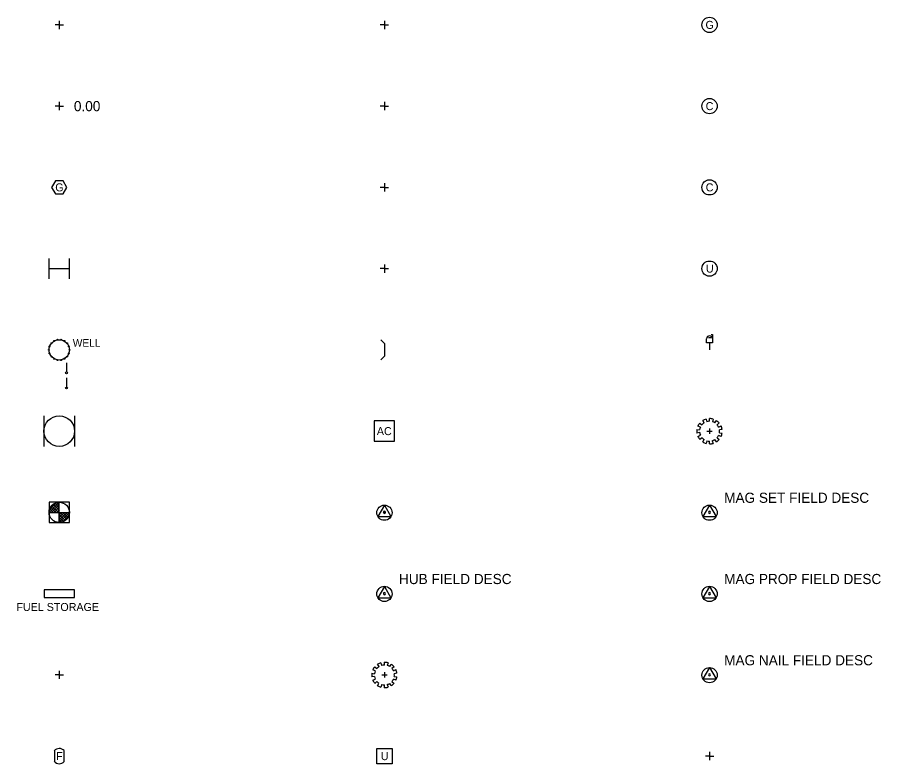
# Model space of a CAD drawing. Extents: x 91 to 2906, y -24 to 912.
# Drawn here: x 874 to 1405, y -5 to 455 of the extents above; entities that cross this region are included whole.
import ezdxf

# ---------------------------------------------------------------- set-up
doc = ezdxf.new("R2010")
doc.units = 0
for name, color, linetype in [('Default', 7, 'Continuous'), ('V-BECH-OHWM', 7, 'Continuous'), ('V-COMM-MHOL', 7, 'Continuous'), ('V-FUEL-DEVC', 7, 'Continuous'), ('V-FUEL-JBOX', 7, 'Continuous'), ('V-FUEL-METR', 7, 'Continuous'), ('V-FUEL-TANK', 7, 'Continuous'), ('V-FUEL-VALT', 7, 'Continuous'), ('V-LITE-EXTR', 7, 'Continuous'), ('V-SITE-FENC', 7, 'Continuous'), ('V-SITE-OTLN', 7, 'Continuous'), ('V-SITE-VEGE', 7, 'Continuous'), ('V-SSWR-IDEN', 7, 'Continuous'), ('V-STRM-HWAL', 7, 'Continuous'), ('V-STRM-IDEN', 7, 'Continuous'), ('V-SURV-DATA', 7, 'Continuous'), ('V-TOPO-SPOT', 7, 'Continuous'), ('V-UTIL-IDEN', 7, 'Continuous'), ('V-UTIL-JBOX', 7, 'Continuous'), ('V-UTIL-MHOL', 7, 'Continuous')]:
    doc.layers.add(name, color=color, linetype=linetype)

# ---------------------------------------------------------------- blocks, each defined once
blk = doc.blocks.new('SurveyPointCell')
at = {"layer": 'Default'}
for p, q in [((-0.5, 0), (0.5, 0)), ((0, -0.5), (0, 0.5))]:
    blk.add_line(p, q, dxfattribs=at)
blk.add_circle((0, 0), 0.5, dxfattribs=at)

msp = doc.modelspace()

# ---------------------------------------------------------------- linework, layer by layer
at = {"layer": 'V-BECH-OHWM'}
for p, q in [((1100, 300), (1097.46, 300)), ((1100, 302.55), (1100, 297.46)), ((1100, 300), (1102.55, 300))]:
    msp.add_line(p, q, dxfattribs=at)
at = {"layer": 'V-COMM-MHOL'}
for centre in [(1300, 400), (1300, 350)]:
    msp.add_circle(centre, 4.69, dxfattribs=at)
at = {"layer": 'V-FUEL-DEVC'}
for p, q in [((896.82, 255.5), (896.82, 255.5)), ((898.9, 256.25), (898.9, 256.25)), ((901.11, 256.25), (901.11, 256.25)), ((903.18, 255.5), (903.18, 255.5)), ((893.65, 250), (893.65, 250)), ((894.03, 252.18), (894.03, 252.18)), ((895.13, 254.09), (895.13, 254.09)), ((904.87, 254.09), (904.87, 254.09)), ((905.97, 252.18), (905.97, 252.18)), ((906.35, 250), (906.35, 250)), ((894.03, 247.82), (894.03, 247.82)), ((895.13, 245.91), (895.13, 245.91)), ((896.82, 244.5), (896.82, 244.5)), ((903.18, 244.5), (903.18, 244.5)), ((904.87, 245.91), (904.87, 245.91)), ((905.97, 247.82), (905.97, 247.82)), ((898.9, 243.75), (898.9, 243.75)), ((901.11, 243.75), (901.11, 243.75)), ((904.42, 242.06), (904.42, 236.41)), ((904.42, 232.76), (904.42, 227.11)), ((890.59, 209.41), (890.59, 190.59)), ((909.41, 209.41), (909.41, 190.59)), ((900, 50), (897.46, 50)), ((900, 52.55), (900, 47.46)), ((900, 50), (902.55, 50))]:
    msp.add_line(p, q, dxfattribs=at)
for centre, radius in [((900, 250), 6.24), ((896.83, 255.5), 0.282), ((898.9, 256.25), 0.282), ((901.1, 256.25), 0.282), ((903.18, 255.5), 0.282), ((893.65, 250), 0.282), ((894.03, 252.17), 0.282), ((895.14, 254.08), 0.282), ((904.86, 254.08), 0.282), ((905.97, 252.17), 0.282), ((906.35, 250), 0.282), ((894.03, 247.83), 0.282), ((895.14, 245.92), 0.282), ((896.83, 244.5), 0.282), ((903.18, 244.5), 0.282), ((904.86, 245.92), 0.282), ((905.97, 247.83), 0.282), ((898.9, 243.75), 0.282), ((901.1, 243.75), 0.282), ((904.42, 235.85), 0.564), ((904.42, 226.54), 0.564), ((900, 200), 9.4)]:
    msp.add_circle(centre, radius, dxfattribs=at)
at = {"layer": 'V-FUEL-JBOX'}
msp.add_circle((1300, 450), 4.69, dxfattribs=at)
at = {"layer": 'V-FUEL-METR'}
msp.add_lwpolyline([(902.34, 345.94), (904.69, 350), (902.34, 354.06), (897.66, 354.06), (895.31, 350), (897.66, 345.94)], close=True, dxfattribs=at)
at = {"layer": 'V-FUEL-TANK'}
msp.add_lwpolyline([(890.62, 102.34), (890.62, 97.66), (909.38, 97.66), (909.38, 102.34)], close=True, dxfattribs=at)
at = {"layer": 'V-FUEL-VALT'}
for points in [[(896.97, 3.19), (896.97, -3.19)], [(903.03, -3.36), (903.03, 3.36)]]:
    msp.add_lwpolyline(points, dxfattribs=at)
for centre, start, end in [((900.07, 0.73), 41.5928, 141.618), ((900.07, -0.73), 218.382, 318.4072)]:
    msp.add_arc(centre, 3.96, start, end, dxfattribs=at)
at = {"layer": 'V-LITE-EXTR'}
for p, q in [((900, 452.55), (900, 447.46)), ((900, 450), (897.46, 450)), ((900, 450), (902.55, 450))]:
    msp.add_line(p, q, dxfattribs=at)
at = {"layer": 'V-SITE-FENC'}
for p, q in [((893.73, 293.73), (893.73, 306.27)), ((906.27, 293.73), (906.27, 306.27)), ((893.73, 300), (906.27, 300))]:
    msp.add_line(p, q, dxfattribs=at)
at = {"layer": 'V-SITE-OTLN'}
for p, q in [((1299.3, 257.6), (1300.7, 257.6)), ((1301.02, 259.38), (1301.82, 259.38)), ((1300, 254.34), (1300, 250)), ((900, 156.24), (893.76, 150)), ((898.15, 155.96), (894.04, 151.85)), ((900, 154.87), (895.13, 150)), ((895.27, 154.07), (899.34, 150.06)), ((896.34, 154.99), (900, 151.27)), ((897.24, 155.59), (900, 152.82)), ((898.32, 156.01), (900, 154.32)), ((900, 143.76), (900, 156.24)), ((893.76, 150), (906.24, 150)), ((893.8, 150.74), (894.54, 150)), ((894.12, 152.1), (896.22, 150)), ((894.64, 153.2), (897.83, 150)), ((900, 153.19), (896.81, 150)), ((900, 151.5), (898.5, 150)), ((900, 143.76), (906.24, 150)), ((900, 148.5), (901.5, 150)), ((900, 145.19), (904.81, 150)), ((900, 146.87), (903.13, 150)), ((904.68, 145.87), (900.53, 150)), ((905.28, 146.76), (902.11, 150)), ((905.83, 147.89), (903.72, 150)), ((906.18, 149.16), (905.34, 150)), ((903.6, 145.01), (900, 148.67)), ((902.69, 144.37), (900, 147.12)), ((901.56, 143.99), (900, 145.62)), ((901.86, 144.04), (905.95, 148.14)), ((1300, 2.55), (1300, -2.54)), ((1300, 0), (1297.46, 0)), ((1300, 0), (1302.55, 0))]:
    msp.add_line(p, q, dxfattribs=at)
msp.add_lwpolyline([(1301.82, 259.38), (1301.82, 254.34), (1298.18, 254.34), (1298.18, 256.86)], dxfattribs=at)
for points in [[(1093.75, 193.75), (1106.25, 193.75), (1106.25, 206.25), (1093.75, 206.25)], [(893.76, 156.24), (893.76, 143.76), (906.24, 143.76), (906.24, 156.24)]]:
    msp.add_lwpolyline(points, close=True, dxfattribs=at)
msp.add_circle((900, 150), 6.24, dxfattribs=at)
msp.add_arc((1300, 256.86), 1.82, 0, 180, dxfattribs=at)
at = {"layer": 'V-SITE-VEGE'}
for p, q in [((1297.86, 207.43), (1298.28, 205.79)), ((1300.02, 206.04), (1300.06, 207.73)), ((1302.25, 207.41), (1301.78, 205.78)), ((1294.41, 202.4), (1292.87, 203.08)), ((1294.04, 204.97), (1295.31, 203.84)), ((1296.74, 205.1), (1295.8, 206.51)), ((1303.3, 205.08), (1304.24, 206.47)), ((1305.93, 205.01), (1304.67, 203.9)), ((1305.59, 202.46), (1307.09, 203.21)), ((1292.25, 200.98), (1293.92, 200.7)), ((1293.94, 199.06), (1292.27, 198.76)), ((1292.89, 196.68), (1294.41, 197.43)), ((1298.35, 200), (1301.65, 200)), ((1300, 201.65), (1300, 198.35)), ((1307.11, 196.66), (1305.54, 197.3)), ((1306.06, 199), (1307.75, 198.8)), ((1307.75, 201), (1306.08, 200.73)), ((1295.4, 195.89), (1294.11, 194.78)), ((1295.82, 193.32), (1296.64, 194.78)), ((1298.35, 194.02), (1297.88, 192.41)), ((1300.02, 192.1), (1300.02, 193.79)), ((1301.69, 194.04), (1302.22, 192.43)), ((1304.24, 193.36), (1303.34, 194.78)), ((1304.6, 195.87), (1305.91, 194.78)), ((1094.04, 54.97), (1095.31, 53.84)), ((1096.74, 55.1), (1095.8, 56.51)), ((1097.86, 57.43), (1098.28, 55.79)), ((1100.02, 56.04), (1100.06, 57.73)), ((1102.25, 57.41), (1101.78, 55.78)), ((1103.3, 55.08), (1104.24, 56.47)), ((1105.93, 55.01), (1104.67, 53.9)), ((1105.59, 52.46), (1107.09, 53.21)), ((1092.25, 50.98), (1093.92, 50.7)), ((1093.94, 49.06), (1092.27, 48.76)), ((1094.41, 52.4), (1092.87, 53.08)), ((1098.35, 50), (1101.65, 50)), ((1100, 51.65), (1100, 48.35)), ((1106.06, 49), (1107.75, 48.8)), ((1107.75, 51), (1106.08, 50.73)), ((1092.89, 46.68), (1094.41, 47.43)), ((1095.4, 45.89), (1094.11, 44.78)), ((1095.82, 43.32), (1096.64, 44.78)), ((1098.35, 44.02), (1097.88, 42.41)), ((1100.02, 42.1), (1100.02, 43.79)), ((1101.69, 44.04), (1102.22, 42.43)), ((1104.24, 43.36), (1103.34, 44.78)), ((1104.6, 45.87), (1105.91, 44.78)), ((1107.11, 46.66), (1105.54, 47.3))]:
    msp.add_line(p, q, dxfattribs=at)
for centre, radius, start, end in [((1300, 199.92), 7.81, 105.972, 122.5562), ((1300, 199.92), 7.81, 73.2952, 89.5718), ((1300, 199.92), 7.81, 139.7777, 156.0738), ((1300, 199.92), 6.12, 156.0557, 172.7558), ((1300, 199.92), 6.12, 122.254, 140.086), ((1300, 199.92), 6.12, 89.9461, 106.3473), ((1300, 199.92), 6.12, 57.451, 73.0843), ((1300, 199.92), 7.81, 40.7122, 57.1166), ((1300, 199.92), 6.12, 24.4529, 40.4774), ((1300, 199.92), 7.81, 7.9671, 24.8625), ((1300, 199.92), 7.81, 172.27, 188.583), ((1300, 199.92), 7.81, 204.5394, 220.9852), ((1300, 199.92), 6.12, 188.0619, 204.0332), ((1300, 199.92), 6.12, 318.6432, 334.5795), ((1300, 199.92), 6.12, 351.5431, 7.6203), ((1300, 199.92), 7.81, 335.3123, 351.7042), ((1300, 199.92), 6.12, 221.2062, 236.7795), ((1300, 199.92), 7.81, 237.6108, 254.1981), ((1300, 199.92), 6.12, 254.31, 270.043), ((1300, 199.92), 7.81, 270.0356, 286.342), ((1300, 199.92), 6.12, 285.9559, 303.0564), ((1300, 199.92), 7.81, 302.8434, 319.0222), ((1100, 49.92), 7.81, 139.7777, 156.0738), ((1100, 49.92), 6.12, 122.254, 140.086), ((1100, 49.92), 7.81, 105.972, 122.5562), ((1100, 49.92), 6.12, 89.9461, 106.3473), ((1100, 49.92), 7.81, 73.2952, 89.5718), ((1100, 49.92), 6.12, 57.451, 73.0843), ((1100, 49.92), 7.81, 40.7122, 57.1166), ((1100, 49.92), 6.12, 24.4529, 40.4774), ((1100, 49.92), 7.81, 7.9671, 24.8625), ((1100, 49.92), 7.81, 172.27, 188.583), ((1100, 49.92), 6.12, 156.0557, 172.7558), ((1100, 49.92), 6.12, 188.0619, 204.0332), ((1100, 49.92), 6.12, 351.5431, 7.6203), ((1100, 49.92), 7.81, 335.3123, 351.7042), ((1100, 49.92), 7.81, 204.5394, 220.9852), ((1100, 49.92), 6.12, 221.2062, 236.7795), ((1100, 49.92), 7.81, 237.6108, 254.1981), ((1100, 49.92), 6.12, 254.31, 270.043), ((1100, 49.92), 6.12, 285.9559, 303.0564), ((1100, 49.92), 7.81, 302.8434, 319.0222), ((1100, 49.92), 6.12, 318.6432, 334.5795), ((1100, 49.92), 7.81, 270.0356, 286.342)]:
    msp.add_arc(centre, radius, start, end, dxfattribs=at)
at = {"layer": 'V-SSWR-IDEN'}
for p, q in [((1100, 452.55), (1100, 447.46)), ((1100, 450), (1097.46, 450)), ((1100, 450), (1102.55, 450))]:
    msp.add_line(p, q, dxfattribs=at)
at = {"layer": 'V-STRM-HWAL'}
msp.add_lwpolyline([(1097.79, 256.12), (1100, 253.91), (1100, 246.09), (1097.79, 243.88)], dxfattribs=at)
at = {"layer": 'V-STRM-IDEN'}
for p, q in [((1100, 400), (1097.46, 400)), ((1100, 402.55), (1100, 397.46)), ((1100, 400), (1102.55, 400))]:
    msp.add_line(p, q, dxfattribs=at)
at = {"layer": 'V-SURV-DATA'}
for p, q in [((1100, 154.48), (1095.95, 147.46)), ((1100, 154.48), (1095.95, 147.46)), ((1100, 154.48), (1104.05, 147.46)), ((1100, 154.48), (1104.05, 147.46)), ((1300, 154.48), (1295.95, 147.46)), ((1300, 154.48), (1304.05, 147.46)), ((1095.95, 147.46), (1104.05, 147.46)), ((1095.95, 147.46), (1104.05, 147.46)), ((1295.95, 147.46), (1304.05, 147.46)), ((1100, 104.48), (1095.95, 97.46)), ((1100, 104.48), (1104.05, 97.46)), ((1300, 104.48), (1295.95, 97.46)), ((1300, 104.48), (1304.05, 97.46)), ((1095.95, 97.46), (1104.05, 97.46)), ((1295.95, 97.46), (1304.05, 97.46)), ((1300, 54.48), (1295.95, 47.46)), ((1300, 54.48), (1304.05, 47.46)), ((1295.95, 47.46), (1304.05, 47.46))]:
    msp.add_line(p, q, dxfattribs=at)
for centre in [(1100, 149.8), (1100, 149.8), (1300, 149.8), (1100, 99.8), (1300, 99.8), (1300, 49.8)]:
    msp.add_circle(centre, 4.69, dxfattribs=at)
for centre in [(1100, 150), (1100, 150), (1300, 150), (1100, 100), (1300, 100), (1300, 50)]:
    msp.add_arc(centre, 0.65, 92.2877, 90.5674, dxfattribs=at)
at = {"layer": 'V-TOPO-SPOT'}
for p, q in [((900, 400), (897.46, 400)), ((900, 402.55), (900, 397.46)), ((900, 400), (902.55, 400))]:
    msp.add_line(p, q, dxfattribs=at)
at = {"layer": 'V-UTIL-IDEN'}
for p, q in [((1100, 352.55), (1100, 347.46)), ((1100, 350), (1097.46, 350)), ((1100, 350), (1102.55, 350))]:
    msp.add_line(p, q, dxfattribs=at)
at = {"layer": 'V-UTIL-JBOX'}
msp.add_lwpolyline([(1095.31, 4.69), (1104.69, 4.69), (1104.69, -4.69), (1095.31, -4.69)], close=True, dxfattribs=at)
at = {"layer": 'V-UTIL-MHOL'}
msp.add_circle((1300, 300), 4.69, dxfattribs=at)

# ---------------------------------------------------------------- block references
at = {"layer": 'Default'}
msp.add_blockref('SurveyPointCell', (1100, 150), dxfattribs=at)
msp.add_blockref('SurveyPointCell', (1100, 150), dxfattribs=at)

# ---------------------------------------------------------------- texts
at = {"layer": 'V-COMM-MHOL'}
for p in [(1297.65, 397.54), (1297.65, 347.54)]:
    msp.add_text('C', height=4.92, dxfattribs=at).set_placement(p)
at = {"layer": 'V-FUEL-DEVC'}
msp.add_text('WELL', height=4.68, dxfattribs=at).set_placement((908.31, 251.93))
at = {"layer": 'V-FUEL-JBOX'}
msp.add_text('G', height=4.92, dxfattribs=at).set_placement((1297.54, 447.54))
at = {"layer": 'V-FUEL-METR'}
msp.add_text('G', height=4.92, dxfattribs=at).set_placement((897.54, 347.54))
at = {"layer": 'V-FUEL-TANK'}
msp.add_text('FUEL STORAGE', height=4.9213, dxfattribs=at).set_placement((873.63, 89.32))
at = {"layer": 'V-FUEL-VALT'}
msp.add_text('F', height=4.92, dxfattribs=at).set_placement((898.06, -2.46))
at = {"layer": 'V-SITE-OTLN'}
msp.add_text('AC', height=4.921, dxfattribs=at).set_placement((1095.36, 197.54))
at = {"layer": 'V-SURV-DATA'}
for s, p in [('MAG SET FIELD DESC', (1309, 155.87)), ('HUB FIELD DESC', (1109, 105.87)), ('MAG PROP FIELD DESC', (1309, 105.87)), ('MAG NAIL FIELD DESC', (1309, 55.87))]:
    msp.add_text(s, height=6.252, dxfattribs=at).set_placement(p)
at = {"layer": 'V-TOPO-SPOT'}
msp.add_text('0.00', height=6.252, dxfattribs=at).set_placement((909, 396.87))
at = {"layer": 'V-UTIL-JBOX'}
msp.add_text('U', height=4.92, dxfattribs=at).set_placement((1097.79, -2.46))
at = {"layer": 'V-UTIL-MHOL'}
msp.add_text('U', height=4.92, dxfattribs=at).set_placement((1297.79, 297.54))

doc.saveas('drawing.dxf')
